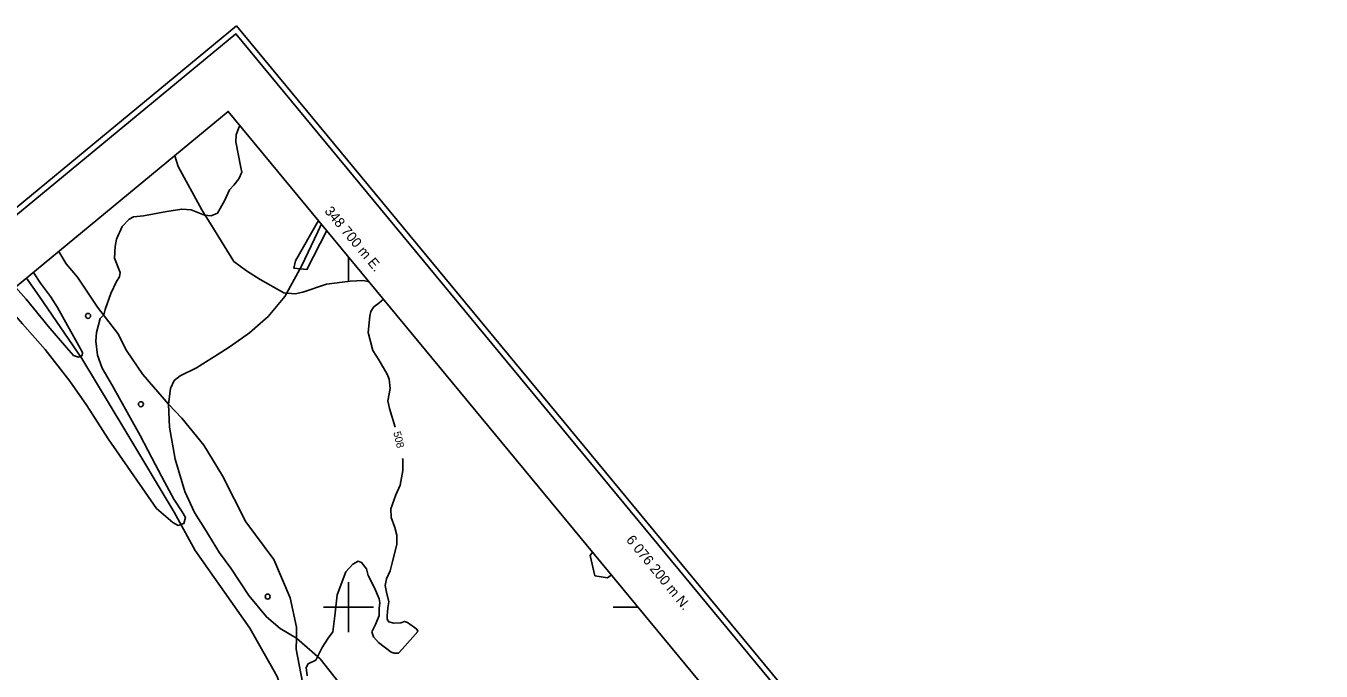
# Model space of a CAD drawing. Extents: x 347312 to 350503, y 6073086 to 6076432.
# Drawn here: x 348571 to 349088, y 6076174 to 6076432 of the extents above; entities that cross this region are included whole.
import ezdxf

# ---------------------------------------------------------------- set-up
doc = ezdxf.new("R2010")
doc.units = 0
for name, color, linetype in [('Level 2', 7, 'Continuous'), ('Level 22', 7, 'Continuous'), ('Level 36', 7, 'Continuous'), ('Level 4', 7, 'Continuous'), ('Level 44', 7, 'Continuous'), ('Level 60', 7, 'Continuous'), ('Level 61', 7, 'Continuous')]:
    doc.layers.add(name, color=color, linetype=linetype)

msp = doc.modelspace()

# ---------------------------------------------------------------- linework, layer by layer
at = {"layer": 'Level 2'}
for points in [[(348599.51, 6076309.51), (348600.96, 6076315.12), (348602.4, 6076316.63), (348602.99, 6076318.78), (348605.3, 6076325.12), (348607.49, 6076329.87), (348608.73, 6076331.76), (348609.01, 6076333.49), (348606.72, 6076339.15), (348607, 6076343.89), (348607.51, 6076346.78), (348609.72, 6076351.82), (348612.51, 6076354.76), (348614.33, 6076355.65), (348618.25, 6076356.03), (348627.56, 6076357.77), (348633.5, 6076358.8), (348637.3, 6076358.52), (348642.64, 6076356.3), (348645.19, 6076356.05), (348647.77, 6076357.18), (348650.56, 6076362.03), (348652.58, 6076366.49), (348654.26, 6076368.35), (348656.29, 6076370.91), (348657.44, 6076373.54), (348657.06, 6076375.4), (348655.11, 6076385.57), (348655.25, 6076388.42), (348656.34, 6076391.27), (348656.77, 6076392.09)], [(348567.29, 6076327.67), (348571.53, 6076322.85), (348580.2, 6076312.03), (348587.57, 6076303.5), (348590.35, 6076300.43), (348592.35, 6076299.7), (348593.84, 6076300.39), (348593.89, 6076301.57), (348592.54, 6076304.23), (348586.64, 6076314.71), (348583.99, 6076319.52), (348581.24, 6076323.97), (348577.14, 6076329.18), (348574.38, 6076333.49), (348574.36, 6076333.51)], [(348561.54, 6076322.91), (348562.63, 6076321.5), (348570.07, 6076313.05), (348579.06, 6076302.81), (348588.96, 6076290.08), (348595.72, 6076280.36), (348604.12, 6076267.16), (348623.47, 6076239.38), (348629.95, 6076233.78), (348632.07, 6076232.6), (348634.38, 6076233.36), (348635.01, 6076235.68), (348633.72, 6076237.97), (348630.36, 6076243.12), (348626.62, 6076249.99), (348623.09, 6076256.76), (348616.92, 6076268.49), (348612.38, 6076276.58), (348605.85, 6076288.26), (348601.82, 6076295.29), (348599.87, 6076300.56), (348599.33, 6076306.09), (348599.51, 6076309.51)], [(348708.46, 6076316.11), (348708.89, 6076317.98), (348710.12, 6076319.72), (348712.14, 6076321.19), (348714.02, 6076322.8)], [(348718.6, 6076271.74), (348716.41, 6076279.26), (348715.75, 6076282.23), (348716.56, 6076287.14), (348716.26, 6076290.97), (348715.45, 6076292.86), (348712.13, 6076298.58), (348709.7, 6076302.35), (348707.89, 6076309.5), (348708.46, 6076316.11)], [(348683.56, 6076172.63), (348683.15, 6076175.95), (348683.92, 6076177.43), (348686.98, 6076178.87), (348689.54, 6076183.88), (348691.88, 6076187.66), (348693.74, 6076190.08), (348694.59, 6076196.53), (348695.52, 6076204.94), (348698.98, 6076214.05), (348701.78, 6076217.14), (348703.86, 6076218.37), (348705.2, 6076217.76), (348707.22, 6076215.27), (348707.9, 6076212.59), (348710.39, 6076207.65), (348712.26, 6076203.27), (348712.51, 6076201.72), (348712.27, 6076199.47), (348712.28, 6076196.62), (348710.84, 6076193.07), (348709.37, 6076190.18), (348709.95, 6076188.09), (348711.91, 6076185.82), (348717.06, 6076182.08), (348718.27, 6076181.62), (348719.89, 6076181.65), (348722.6, 6076184.52), (348727.65, 6076190.22), (348727.21, 6076191.2), (348723.59, 6076193.81), (348722.37, 6076194.26), (348720.94, 6076193.71), (348718.06, 6076193.56), (348716.12, 6076194.07), (348715.47, 6076195.14), (348715.42, 6076196.46), (348715.74, 6076199.73), (348716.14, 6076202.11), (348715.17, 6076205.91), (348714.57, 6076208.66), (348715.14, 6076211.33), (348716.62, 6076214.51), (348717.49, 6076218.25), (348719.24, 6076224.92), (348719.23, 6076228.73), (348718.43, 6076231.71), (348716.97, 6076235.77), (348716.93, 6076239.14), (348718.82, 6076244.85), (348720.64, 6076248.59), (348721.67, 6076254.51), (348721.63, 6076258.83), (348721.54, 6076259.33)]]:
    msp.add_lwpolyline(points, dxfattribs=at)
at = {"layer": 'Level 22'}
for points in [[(348699.58, 6076165.57), (348688.71, 6076179.38), (348679.25, 6076187.61), (348672.73, 6076191.41), (348667.28, 6076196.11), (348660.27, 6076204.62), (348653.06, 6076215.52), (348648.53, 6076221.62), (348642.67, 6076231.27), (348638.57, 6076237.74), (348634.72, 6076246.07), (348630.85, 6076259.05), (348628.58, 6076271.73), (348628.22, 6076280.91), (348629.07, 6076287.2), (348630.48, 6076290.35), (348632.92, 6076292.26), (348639.37, 6076295.46), (348649.08, 6076301.56), (348652.86, 6076303.93), (348660.48, 6076309.39), (348667.99, 6076315.97), (348674.68, 6076323.96), (348681.27, 6076336.07), (348687.75, 6076349.67), (348689.18, 6076352.86)], [(348686.96, 6076134.42), (348684.58, 6076151.5), (348682.36, 6076166.62), (348679.2, 6076183.21), (348679.25, 6076187.61), (348679.29, 6076192.01), (348676.69, 6076203.65), (348670.26, 6076218.96), (348659.09, 6076234.03), (348649.73, 6076252.3), (348642.38, 6076264.6), (348633.61, 6076275.39), (348628.22, 6076280.91), (348617.98, 6076292.73), (348611.47, 6076302.43), (348608.05, 6076309.18), (348599.97, 6076319.68), (348591.93, 6076331.56), (348587.41, 6076336.94), (348584.51, 6076341.89)]]:
    msp.add_lwpolyline(points, dxfattribs=at)
at = {"layer": 'Level 36'}
for centre in [(348596.18, 6076316.17), (348617.25, 6076280.95), (348667.78, 6076204.19)]:
    msp.add_circle(centre, 1, dxfattribs=at)
at = {"layer": 'Level 4'}
for points in [[(348708.3, 6076329.73), (348705.96, 6076330.3), (348700.62, 6076330.07), (348691.28, 6076328.79), (348681.83, 6076325.61), (348678.76, 6076324.98), (348674.29, 6076325.4), (348664.85, 6076330.75), (348659.32, 6076334.12), (348654.35, 6076337.9), (348646.6, 6076350.32), (348641.59, 6076358.43), (348632.13, 6076375.74), (348630.72, 6076380.08)], [(348662.5, 6076093.85), (348671.11, 6076134.25), (348673.96, 6076156.54), (348674.3, 6076164.34), (348671.55, 6076172.25), (348660.65, 6076191.63), (348638.84, 6076222.56), (348630.52, 6076237.81), (348611.23, 6076270.03), (348593.64, 6076299.17), (348576.64, 6076324.03), (348571.57, 6076331.2)]]:
    msp.add_lwpolyline(points, dxfattribs=at)
at = {"layer": 'Level 44'}
for points in [[(348688.04, 6076354.25), (348678.85, 6076338.19), (348678.2, 6076335.23), (348683.43, 6076334.7), (348691.39, 6076350.19)], [(348797.36, 6076221.95), (348796.37, 6076220.64), (348798.28, 6076212.5), (348803.31, 6076211.66), (348804.83, 6076212.91)]]:
    msp.add_lwpolyline(points, dxfattribs=at)
at = {"layer": 'Level 60'}
for p, q in [((348700, 6076339.77), (348700, 6076329.77)), ((348805.5, 6076200), (348815.5, 6076200))]:
    msp.add_line(p, q, dxfattribs=at)
for points in [[(348655.35, 6076431.86), (347312.14, 6075321.93)], [(350502.67, 6074196.28), (348655.35, 6076431.86)]]:
    msp.add_lwpolyline(points, dxfattribs=at)
for points in [[(349159.76, 6073089.49), (347315.28, 6075321.63), (348655.04, 6076428.72), (350499.52, 6074196.58)], [(348779.44, 6073584.28), (350085.28, 6074663.34), (348652.09, 6076397.74), (347346.25, 6075318.68)]]:
    msp.add_lwpolyline(points, close=True, dxfattribs=at)
at = {"layer": 'Level 61'}
for p, q in [((348700, 6076210), (348700, 6076190)), ((348690, 6076200), (348710, 6076200))]:
    msp.add_line(p, q, dxfattribs=at)

# ---------------------------------------------------------------- texts
at = {"layer": 'Level 2'}
msp.add_text('508', height=3, rotation=283.4809, dxfattribs=at).set_placement((348717.86, 6076269.72))
at = {"layer": 'Level 61'}
for s, rotation, p in [('348 700 m E. ', 309.813, (348690.23, 6076357.87)), ('6 076 200 m N.', 309.3644, (348810.5, 6076226.7))]:
    msp.add_text(s, height=4, rotation=rotation, dxfattribs=at).set_placement(p)

doc.saveas('drawing.dxf')
